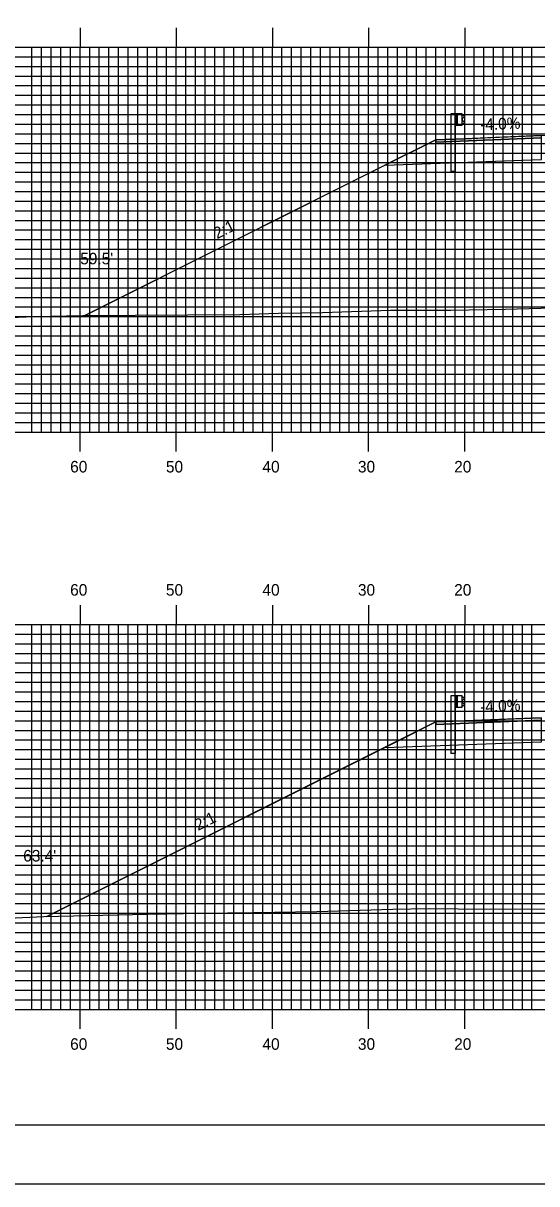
# Model space of a CAD drawing. Extents: x 1760217 to 1760560, y 442591 to 442811.
# Drawn here: x 1760316.8 to 1760370.2, y 442590.5 to 442711.2 of the extents above; entities that cross this region are included whole.
import ezdxf

# ---------------------------------------------------------------- set-up
doc = ezdxf.new("R2010")
doc.units = 0
for name, color, linetype in [('ANNOTATION', 7, 'Continuous'), ('BORDER', 7, 'Continuous'), ('D_Guardrail_Beam_Lt', 7, 'Continuous'), ('D_Roadway_Centerline', 7, 'Continuous'), ('D_Roadway_Edge_Shoulder', 7, 'Continuous'), ('D_Roadway_SlopeLines', 7, 'Continuous'), ('D_Roadway_SubGrade', 7, 'Continuous'), ('D_Text_Standard', 7, 'Continuous'), ('H_V ANNOTATION', 7, 'Continuous'), ('MAJOR', 7, 'Continuous'), ('MINOR', 7, 'Continuous'), ('PLOT BOUNDARY', 7, 'Continuous'), ('S_Roadway_Centerline', 7, 'Continuous')]:
    doc.layers.add(name, color=color, linetype=linetype)

msp = doc.modelspace()

# ---------------------------------------------------------------- linework, layer by layer
at = {"layer": 'BORDER'}
msp.add_lwpolyline([(1760233.1, 442596.67), (1760553.1, 442596.67), (1760553.1, 442806.67), (1760233.1, 442806.67)], close=True, dxfattribs=at)
at = {"layer": 'D_Guardrail_Beam_Lt'}
for p, q in [((1760361.27, 442701.75), (1760361.27, 442695.75)), ((1760361.74, 442701.75), (1760361.27, 442701.75)), ((1760362.43, 442701.75), (1760361.74, 442701.75)), ((1760361.74, 442701.75), (1760361.74, 442700.58)), ((1760361.8, 442701.75), (1760361.8, 442700.58)), ((1760361.91, 442701.75), (1760361.91, 442700.58)), ((1760362.43, 442700.58), (1760362.43, 442701.75)), ((1760362.43, 442701.66), (1760362.5, 442701.65)), ((1760362.43, 442701.2), (1760362.43, 442701.13)), ((1760362.5, 442700.68), (1760362.43, 442700.66)), ((1760362.66, 442701.4), (1760362.47, 442701.26)), ((1760362.47, 442701.06), (1760362.66, 442700.93)), ((1760362.52, 442701.64), (1760362.66, 442701.54)), ((1760362.66, 442700.78), (1760362.52, 442700.68)), ((1760361.74, 442700.58), (1760362.43, 442700.58)), ((1760361.76, 442695.75), (1760361.76, 442700.58)), ((1760361.76, 442695.75), (1760361.27, 442695.75)), ((1760361.27, 442641.25), (1760361.27, 442635.25)), ((1760361.74, 442641.25), (1760361.27, 442641.25)), ((1760362.43, 442641.25), (1760361.74, 442641.25)), ((1760361.74, 442641.25), (1760361.74, 442640.08)), ((1760361.8, 442641.25), (1760361.8, 442640.08)), ((1760361.91, 442641.25), (1760361.91, 442640.08)), ((1760362.43, 442640.08), (1760362.43, 442641.25)), ((1760362.43, 442641.16), (1760362.5, 442641.15)), ((1760362.43, 442640.7), (1760362.43, 442640.63)), ((1760362.66, 442640.9), (1760362.47, 442640.76)), ((1760362.47, 442640.56), (1760362.66, 442640.43)), ((1760362.52, 442641.14), (1760362.66, 442641.04)), ((1760361.74, 442640.08), (1760362.43, 442640.08)), ((1760361.76, 442635.25), (1760361.76, 442640.08)), ((1760362.5, 442640.18), (1760362.43, 442640.16)), ((1760362.66, 442640.28), (1760362.52, 442640.18)), ((1760361.76, 442635.25), (1760361.27, 442635.25))]:
    msp.add_line(p, q, dxfattribs=at)
for centre, major_axis, start_param, end_param in [((1760362.51, 442701.2), (-0.0789, 0), 5.323254, 6.283185), ((1760362.51, 442701.13), (-0.0789, 0), 6.283185, 7.243116), ((1760362.5, 442701.61), (0.0417, 0), 0.959931, 1.376053), ((1760362.5, 442700.72), (0.0417, 0), 4.907132, 5.323254), ((1760362.61, 442701.47), (0.0877, 0), 5.323254, 7.243116), ((1760362.61, 442700.86), (0.0877, 0), 5.323254, 7.243116), ((1760362.51, 442640.7), (-0.0789, 0), 5.323254, 6.283185), ((1760362.51, 442640.63), (-0.0789, 0), 6.283185, 7.243116), ((1760362.5, 442641.11), (0.0417, 0), 0.959931, 1.376053), ((1760362.61, 442640.97), (0.0877, 0), 5.323254, 7.243116), ((1760362.61, 442640.36), (0.0877, 0), 5.323254, 7.243116), ((1760362.5, 442640.22), (0.0417, 0), 4.907132, 5.323254)]:
    msp.add_ellipse(centre, major_axis=major_axis, ratio=0.995501, start_param=start_param, end_param=end_param, dxfattribs=at)
at = {"layer": 'D_Roadway_Centerline'}
for points in [[(1760323.21, 442680.8), (1760354.4, 442696.39), (1760354.41, 442696.4), (1760359.7, 442699.04), (1760362.7, 442699.16), (1760365.45, 442699.27), (1760370.7, 442699.48), (1760370.7, 442699.48), (1760382.69, 442699.91), (1760382.7, 442699.91), (1760394.7, 442700.35), (1760394.7, 442700.35), (1760397.13, 442700.43), (1760397.13, 442700.43), (1760405.13, 442700.11), (1760405.13, 442700.11), (1760408.13, 442699.99), (1760409.55, 442699.28), (1760412.88, 442697.62), (1760412.88, 442697.61), (1760443.11, 442682.5)], [(1760319.24, 442618.31), (1760319.25, 442618.31), (1760354.41, 442635.9), (1760355.5, 442636.44), (1760359.7, 442638.54), (1760359.7, 442638.54), (1760361.51, 442638.61), (1760362.7, 442638.66), (1760362.7, 442638.66), (1760368.66, 442638.9), (1760370.7, 442638.98)]]:
    msp.add_lwpolyline(points, dxfattribs=at)
at = {"layer": 'D_Roadway_Edge_Shoulder'}
for points in [[(1760370.7, 442699.48), (1760362.7, 442699.16), (1760362.7, 442699.16), (1760359.7, 442699.04), (1760359.7, 442698.79), (1760370.7, 442699.23)], [(1760370.7, 442638.98), (1760362.7, 442638.66), (1760362.7, 442638.66), (1760359.7, 442638.54), (1760359.7, 442638.29), (1760370.7, 442638.73)]]:
    msp.add_lwpolyline(points, close=True, dxfattribs=at)
at = {"layer": 'D_Roadway_SlopeLines'}
for points in [[(1760359.7, 442699.04), (1760323.21, 442680.8)], [(1760359.7, 442638.54), (1760319.24, 442618.31)]]:
    msp.add_lwpolyline(points, dxfattribs=at)
at = {"layer": 'D_Roadway_SubGrade'}
for points in [[(1760370.7, 442698.82), (1760370.7, 442699.23), (1760359.7, 442698.79), (1760359.7, 442699.04), (1760354.41, 442696.4), (1760370.7, 442696.98)], [(1760370.7, 442638.32), (1760370.7, 442638.73), (1760359.7, 442638.29), (1760359.7, 442638.54), (1760354.41, 442635.9), (1760370.7, 442636.48)]]:
    msp.add_lwpolyline(points, close=True, dxfattribs=at)
at = {"layer": 'MAJOR'}
for p, q in [((1760322.7, 442710.67), (1760322.7, 442708.67)), ((1760332.7, 442710.67), (1760332.7, 442708.67)), ((1760342.7, 442710.67), (1760342.7, 442708.67)), ((1760352.7, 442710.67), (1760352.7, 442708.67)), ((1760362.7, 442710.67), (1760362.7, 442708.67)), ((1760242.7, 442708.67), (1760522.7, 442708.67)), ((1760242.7, 442708.67), (1760522.7, 442708.67)), ((1760322.7, 442668.67), (1760322.7, 442708.67)), ((1760332.7, 442668.67), (1760332.7, 442708.67)), ((1760342.7, 442668.67), (1760342.7, 442708.67)), ((1760352.7, 442668.67), (1760352.7, 442708.67)), ((1760362.7, 442668.67), (1760362.7, 442708.67)), ((1760242.7, 442703.67), (1760522.7, 442703.67)), ((1760242.7, 442698.67), (1760522.7, 442698.67)), ((1760242.7, 442693.67), (1760522.7, 442693.67)), ((1760242.7, 442688.67), (1760522.7, 442688.67)), ((1760242.7, 442683.67), (1760522.7, 442683.67)), ((1760242.7, 442678.67), (1760522.7, 442678.67)), ((1760242.7, 442673.67), (1760522.7, 442673.67)), ((1760242.7, 442668.67), (1760522.7, 442668.67)), ((1760242.7, 442668.67), (1760522.7, 442668.67)), ((1760322.7, 442666.66), (1760322.7, 442668.67)), ((1760332.7, 442666.66), (1760332.7, 442668.67)), ((1760342.7, 442666.66), (1760342.7, 442668.67)), ((1760352.7, 442666.66), (1760352.7, 442668.67)), ((1760362.7, 442666.66), (1760362.7, 442668.67)), ((1760322.7, 442650.67), (1760322.7, 442648.67)), ((1760332.7, 442650.67), (1760332.7, 442648.67)), ((1760342.7, 442650.67), (1760342.7, 442648.67)), ((1760352.7, 442650.67), (1760352.7, 442648.67)), ((1760362.7, 442650.67), (1760362.7, 442648.67)), ((1760242.7, 442648.67), (1760522.7, 442648.67)), ((1760242.7, 442648.67), (1760522.7, 442648.67)), ((1760322.7, 442608.67), (1760322.7, 442648.67)), ((1760332.7, 442608.67), (1760332.7, 442648.67)), ((1760342.7, 442608.67), (1760342.7, 442648.67)), ((1760352.7, 442608.67), (1760352.7, 442648.67)), ((1760362.7, 442608.67), (1760362.7, 442648.67)), ((1760242.7, 442643.67), (1760522.7, 442643.67)), ((1760242.7, 442638.67), (1760522.7, 442638.67)), ((1760242.7, 442633.67), (1760522.7, 442633.67)), ((1760242.7, 442628.67), (1760522.7, 442628.67)), ((1760242.7, 442623.67), (1760522.7, 442623.67)), ((1760242.7, 442618.67), (1760522.7, 442618.67)), ((1760242.7, 442613.67), (1760522.7, 442613.67)), ((1760242.7, 442608.67), (1760522.7, 442608.67)), ((1760242.7, 442608.67), (1760522.7, 442608.67)), ((1760322.7, 442606.66), (1760322.7, 442608.67)), ((1760332.7, 442606.66), (1760332.7, 442608.67)), ((1760342.7, 442606.66), (1760342.7, 442608.67)), ((1760352.7, 442606.66), (1760352.7, 442608.67)), ((1760362.7, 442606.66), (1760362.7, 442608.67))]:
    msp.add_line(p, q, dxfattribs=at)
at = {"layer": 'MINOR'}
for p, q in [((1760317.7, 442668.67), (1760317.7, 442708.67)), ((1760318.7, 442668.67), (1760318.7, 442708.67)), ((1760319.7, 442668.67), (1760319.7, 442708.67)), ((1760320.7, 442668.67), (1760320.7, 442708.67)), ((1760321.7, 442668.67), (1760321.7, 442708.67)), ((1760323.7, 442668.67), (1760323.7, 442708.67)), ((1760324.7, 442668.67), (1760324.7, 442708.67)), ((1760325.7, 442668.67), (1760325.7, 442708.67)), ((1760326.7, 442668.67), (1760326.7, 442708.67)), ((1760327.7, 442668.67), (1760327.7, 442708.67)), ((1760328.7, 442668.67), (1760328.7, 442708.67)), ((1760329.7, 442668.67), (1760329.7, 442708.67)), ((1760330.7, 442668.67), (1760330.7, 442708.67)), ((1760331.7, 442668.67), (1760331.7, 442708.67)), ((1760333.7, 442668.67), (1760333.7, 442708.67)), ((1760334.7, 442668.67), (1760334.7, 442708.67)), ((1760335.7, 442668.67), (1760335.7, 442708.67)), ((1760336.7, 442668.67), (1760336.7, 442708.67)), ((1760337.7, 442668.67), (1760337.7, 442708.67)), ((1760338.7, 442668.67), (1760338.7, 442708.67)), ((1760339.7, 442668.67), (1760339.7, 442708.67)), ((1760340.7, 442668.67), (1760340.7, 442708.67)), ((1760341.7, 442668.67), (1760341.7, 442708.67)), ((1760343.7, 442668.67), (1760343.7, 442708.67)), ((1760344.7, 442668.67), (1760344.7, 442708.67)), ((1760345.7, 442668.67), (1760345.7, 442708.67)), ((1760346.7, 442668.67), (1760346.7, 442708.67)), ((1760347.7, 442668.67), (1760347.7, 442708.67)), ((1760348.7, 442668.67), (1760348.7, 442708.67)), ((1760349.7, 442668.67), (1760349.7, 442708.67)), ((1760350.7, 442668.67), (1760350.7, 442708.67)), ((1760351.7, 442668.67), (1760351.7, 442708.67)), ((1760353.7, 442668.67), (1760353.7, 442708.67)), ((1760354.7, 442668.67), (1760354.7, 442708.67)), ((1760355.7, 442668.67), (1760355.7, 442708.67)), ((1760356.7, 442668.67), (1760356.7, 442708.67)), ((1760357.7, 442668.67), (1760357.7, 442708.67)), ((1760358.7, 442668.67), (1760358.7, 442708.67)), ((1760359.7, 442668.67), (1760359.7, 442708.67)), ((1760360.7, 442668.67), (1760360.7, 442708.67)), ((1760361.7, 442668.67), (1760361.7, 442708.67)), ((1760363.7, 442668.67), (1760363.7, 442708.67)), ((1760364.7, 442668.67), (1760364.7, 442708.67)), ((1760365.7, 442668.67), (1760365.7, 442708.67)), ((1760366.7, 442668.67), (1760366.7, 442708.67)), ((1760367.7, 442668.67), (1760367.7, 442708.67)), ((1760368.7, 442668.67), (1760368.7, 442708.67)), ((1760369.7, 442668.67), (1760369.7, 442708.67)), ((1760242.7, 442707.67), (1760522.7, 442707.67)), ((1760242.7, 442706.67), (1760522.7, 442706.67)), ((1760242.7, 442705.67), (1760522.7, 442705.67)), ((1760242.7, 442704.67), (1760522.7, 442704.67)), ((1760242.7, 442702.67), (1760522.7, 442702.67)), ((1760242.7, 442701.67), (1760522.7, 442701.67)), ((1760242.7, 442700.67), (1760522.7, 442700.67)), ((1760242.7, 442699.67), (1760522.7, 442699.67)), ((1760242.7, 442697.67), (1760522.7, 442697.67)), ((1760242.7, 442696.67), (1760522.7, 442696.67)), ((1760242.7, 442695.67), (1760522.7, 442695.67)), ((1760242.7, 442694.67), (1760522.7, 442694.67)), ((1760242.7, 442692.67), (1760522.7, 442692.67)), ((1760242.7, 442691.67), (1760522.7, 442691.67)), ((1760242.7, 442690.67), (1760522.7, 442690.67)), ((1760242.7, 442689.67), (1760522.7, 442689.67)), ((1760242.7, 442687.67), (1760522.7, 442687.67)), ((1760242.7, 442686.67), (1760522.7, 442686.67)), ((1760242.7, 442685.67), (1760522.7, 442685.67)), ((1760242.7, 442684.67), (1760522.7, 442684.67)), ((1760242.7, 442682.67), (1760522.7, 442682.67)), ((1760242.7, 442681.67), (1760522.7, 442681.67)), ((1760242.7, 442680.67), (1760522.7, 442680.67)), ((1760242.7, 442679.67), (1760522.7, 442679.67)), ((1760242.7, 442677.67), (1760522.7, 442677.67)), ((1760242.7, 442676.67), (1760522.7, 442676.67)), ((1760242.7, 442675.67), (1760522.7, 442675.67)), ((1760242.7, 442674.67), (1760522.7, 442674.67)), ((1760242.7, 442672.67), (1760522.7, 442672.67)), ((1760242.7, 442671.67), (1760522.7, 442671.67)), ((1760242.7, 442670.67), (1760522.7, 442670.67)), ((1760242.7, 442669.67), (1760522.7, 442669.67)), ((1760242.7, 442647.67), (1760522.7, 442647.67)), ((1760317.7, 442608.67), (1760317.7, 442648.67)), ((1760318.7, 442608.67), (1760318.7, 442648.67)), ((1760319.7, 442608.67), (1760319.7, 442648.67)), ((1760320.7, 442608.67), (1760320.7, 442648.67)), ((1760321.7, 442608.67), (1760321.7, 442648.67)), ((1760323.7, 442608.67), (1760323.7, 442648.67)), ((1760324.7, 442608.67), (1760324.7, 442648.67)), ((1760325.7, 442608.67), (1760325.7, 442648.67)), ((1760326.7, 442608.67), (1760326.7, 442648.67)), ((1760327.7, 442608.67), (1760327.7, 442648.67)), ((1760328.7, 442608.67), (1760328.7, 442648.67)), ((1760329.7, 442608.67), (1760329.7, 442648.67)), ((1760330.7, 442608.67), (1760330.7, 442648.67)), ((1760331.7, 442608.67), (1760331.7, 442648.67)), ((1760333.7, 442608.67), (1760333.7, 442648.67)), ((1760334.7, 442608.67), (1760334.7, 442648.67)), ((1760335.7, 442608.67), (1760335.7, 442648.67)), ((1760336.7, 442608.67), (1760336.7, 442648.67)), ((1760337.7, 442608.67), (1760337.7, 442648.67)), ((1760338.7, 442608.67), (1760338.7, 442648.67)), ((1760339.7, 442608.67), (1760339.7, 442648.67)), ((1760340.7, 442608.67), (1760340.7, 442648.67)), ((1760341.7, 442608.67), (1760341.7, 442648.67)), ((1760343.7, 442608.67), (1760343.7, 442648.67)), ((1760344.7, 442608.67), (1760344.7, 442648.67)), ((1760345.7, 442608.67), (1760345.7, 442648.67)), ((1760346.7, 442608.67), (1760346.7, 442648.67)), ((1760347.7, 442608.67), (1760347.7, 442648.67)), ((1760348.7, 442608.67), (1760348.7, 442648.67)), ((1760349.7, 442608.67), (1760349.7, 442648.67)), ((1760350.7, 442608.67), (1760350.7, 442648.67)), ((1760351.7, 442608.67), (1760351.7, 442648.67)), ((1760353.7, 442608.67), (1760353.7, 442648.67)), ((1760354.7, 442608.67), (1760354.7, 442648.67)), ((1760355.7, 442608.67), (1760355.7, 442648.67)), ((1760356.7, 442608.67), (1760356.7, 442648.67)), ((1760357.7, 442608.67), (1760357.7, 442648.67)), ((1760358.7, 442608.67), (1760358.7, 442648.67)), ((1760359.7, 442608.67), (1760359.7, 442648.67)), ((1760360.7, 442608.67), (1760360.7, 442648.67)), ((1760361.7, 442608.67), (1760361.7, 442648.67)), ((1760363.7, 442608.67), (1760363.7, 442648.67)), ((1760364.7, 442608.67), (1760364.7, 442648.67)), ((1760365.7, 442608.67), (1760365.7, 442648.67)), ((1760366.7, 442608.67), (1760366.7, 442648.67)), ((1760367.7, 442608.67), (1760367.7, 442648.67)), ((1760368.7, 442608.67), (1760368.7, 442648.67)), ((1760369.7, 442608.67), (1760369.7, 442648.67)), ((1760242.7, 442646.67), (1760522.7, 442646.67)), ((1760242.7, 442645.67), (1760522.7, 442645.67)), ((1760242.7, 442644.67), (1760522.7, 442644.67)), ((1760242.7, 442642.67), (1760522.7, 442642.67)), ((1760242.7, 442641.67), (1760522.7, 442641.67)), ((1760242.7, 442640.67), (1760522.7, 442640.67)), ((1760242.7, 442639.67), (1760522.7, 442639.67)), ((1760242.7, 442637.67), (1760522.7, 442637.67)), ((1760242.7, 442636.67), (1760522.7, 442636.67)), ((1760242.7, 442635.67), (1760522.7, 442635.67)), ((1760242.7, 442634.67), (1760522.7, 442634.67)), ((1760242.7, 442632.67), (1760522.7, 442632.67)), ((1760242.7, 442631.67), (1760522.7, 442631.67)), ((1760242.7, 442630.67), (1760522.7, 442630.67)), ((1760242.7, 442629.67), (1760522.7, 442629.67)), ((1760242.7, 442627.67), (1760522.7, 442627.67)), ((1760242.7, 442626.67), (1760522.7, 442626.67)), ((1760242.7, 442625.67), (1760522.7, 442625.67)), ((1760242.7, 442624.67), (1760522.7, 442624.67)), ((1760242.7, 442622.67), (1760522.7, 442622.67)), ((1760242.7, 442621.67), (1760522.7, 442621.67)), ((1760242.7, 442620.67), (1760522.7, 442620.67)), ((1760242.7, 442619.67), (1760522.7, 442619.67)), ((1760242.7, 442617.67), (1760522.7, 442617.67)), ((1760242.7, 442616.67), (1760522.7, 442616.67)), ((1760242.7, 442615.67), (1760522.7, 442615.67)), ((1760242.7, 442614.67), (1760522.7, 442614.67)), ((1760242.7, 442612.67), (1760522.7, 442612.67)), ((1760242.7, 442611.67), (1760522.7, 442611.67)), ((1760242.7, 442610.67), (1760522.7, 442610.67)), ((1760242.7, 442609.67), (1760522.7, 442609.67))]:
    msp.add_line(p, q, dxfattribs=at)
at = {"layer": 'PLOT BOUNDARY'}
msp.add_lwpolyline([(1760216.91, 442590.55), (1760556.91, 442590.55), (1760556.91, 442810.55), (1760216.91, 442810.55)], close=True, dxfattribs=at)
at = {"layer": 'S_Roadway_Centerline'}
for points in [[(1760298.09, 442679.84), (1760317.91, 442680.69), (1760322.98, 442680.8), (1760339.33, 442680.88), (1760343.35, 442681.02), (1760347.91, 442681.1), (1760354.98, 442681.33), (1760361.27, 442681.35), (1760366.9, 442681.45), (1760373.11, 442681.62), (1760378.49, 442681.77), (1760383.1, 442681.73), (1760389.84, 442681.68), (1760397.74, 442681.81), (1760401.46, 442681.86), (1760404.67, 442682.02), (1760417.76, 442682.43), (1760419.89, 442682.5), (1760426.19, 442682.62), (1760426.37, 442682.59), (1760427.22, 442682.59), (1760436.62, 442682.48), (1760438.56, 442682.49), (1760447.95, 442682.51)], [(1760312.28, 442618.01), (1760318.93, 442618.31), (1760329.67, 442618.55), (1760335.38, 442618.67), (1760340.7, 442618.73), (1760347.31, 442618.85), (1760355.23, 442619.07), (1760359.02, 442619.17), (1760362.03, 442619.13), (1760370.72, 442619.1), (1760380.67, 442619.37), (1760382.44, 442619.42), (1760383.88, 442619.4), (1760399.59, 442619.6), (1760404.5, 442619.65), (1760404.98, 442619.67), (1760405.57, 442619.69), (1760413.52, 442620.14), (1760414.6, 442620.17), (1760426.44, 442620.62), (1760430.95, 442620.7), (1760440.45, 442620.7), (1760447.81, 442620.91)]]:
    msp.add_lwpolyline(points, dxfattribs=at)

# ---------------------------------------------------------------- texts
at = {"layer": 'ANNOTATION'}
for s, rotation, p in [('-4.0%', 2.2906, (1760364.33, 442700.03)), ('2:1', 26.5642, (1760336.95, 442688.7)), ('-4.0%', 2.2908, (1760364.33, 442639.53)), ('2:1', 26.5645, (1760334.97, 442627.21))]:
    msp.add_text(s, height=1.2, rotation=rotation, dxfattribs=at).set_placement(p)
at = {"layer": 'D_Text_Standard'}
for s, p in [("59.5'", (1760322.72, 442686.1)), ("63.4'", (1760316.79, 442624.04))]:
    msp.add_text(s, height=1.2, dxfattribs=at).set_placement(p)
at = {"layer": 'H_V ANNOTATION'}
for s, p in [('60', (1760321.67, 442664.47)), ('50', (1760331.63, 442664.47)), ('40', (1760341.67, 442664.47)), ('30', (1760351.6, 442664.47)), ('20', (1760361.61, 442664.47)), ('60', (1760321.67, 442651.67)), ('50', (1760331.63, 442651.67)), ('40', (1760341.67, 442651.67)), ('30', (1760351.6, 442651.67)), ('20', (1760361.61, 442651.67)), ('60', (1760321.67, 442604.47)), ('50', (1760331.63, 442604.47)), ('40', (1760341.67, 442604.47)), ('30', (1760351.6, 442604.47)), ('20', (1760361.61, 442604.47))]:
    msp.add_text(s, height=1.2, dxfattribs=at).set_placement(p)

doc.saveas('drawing.dxf')
